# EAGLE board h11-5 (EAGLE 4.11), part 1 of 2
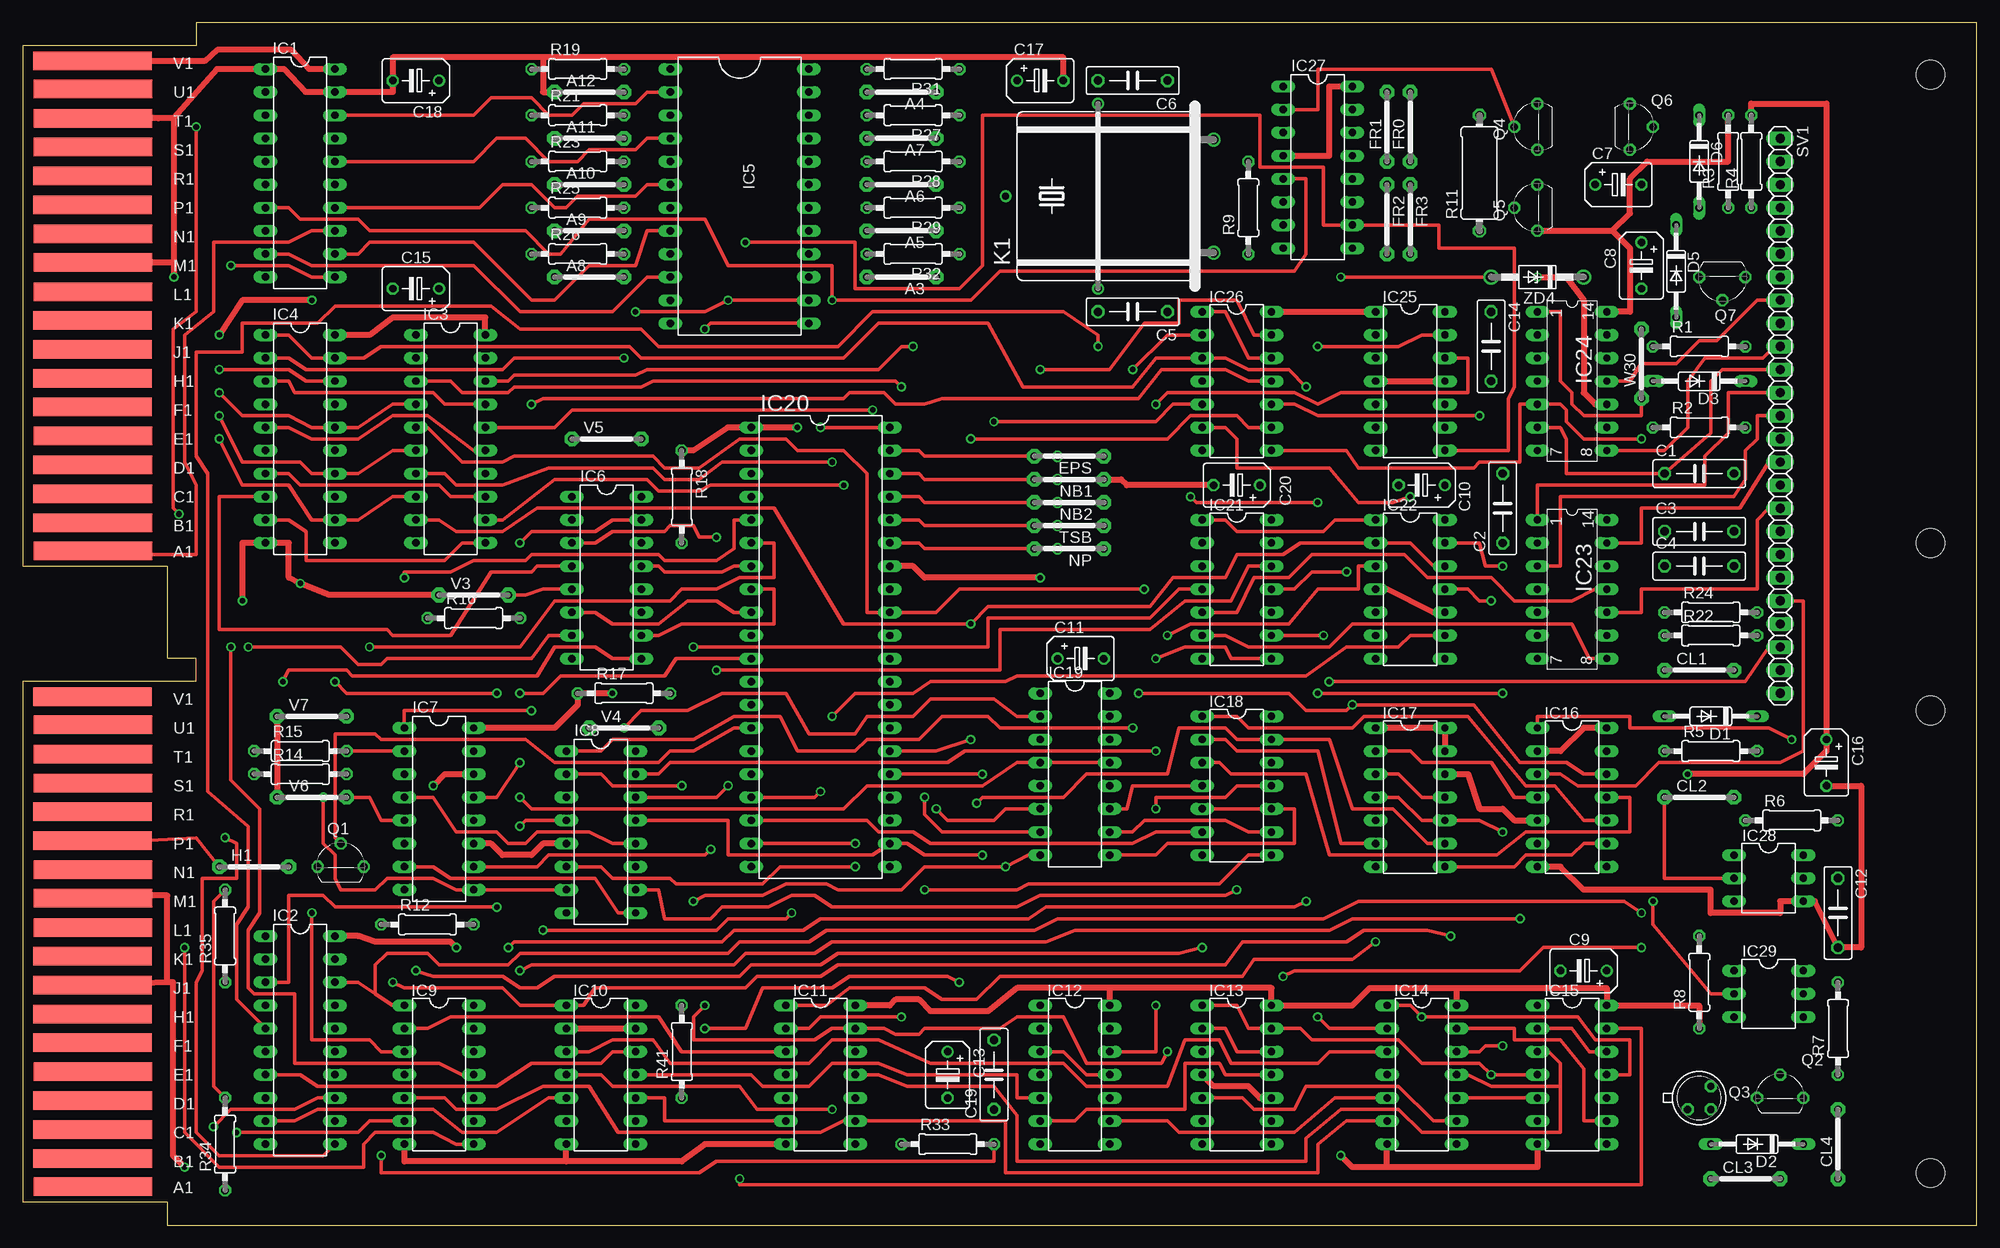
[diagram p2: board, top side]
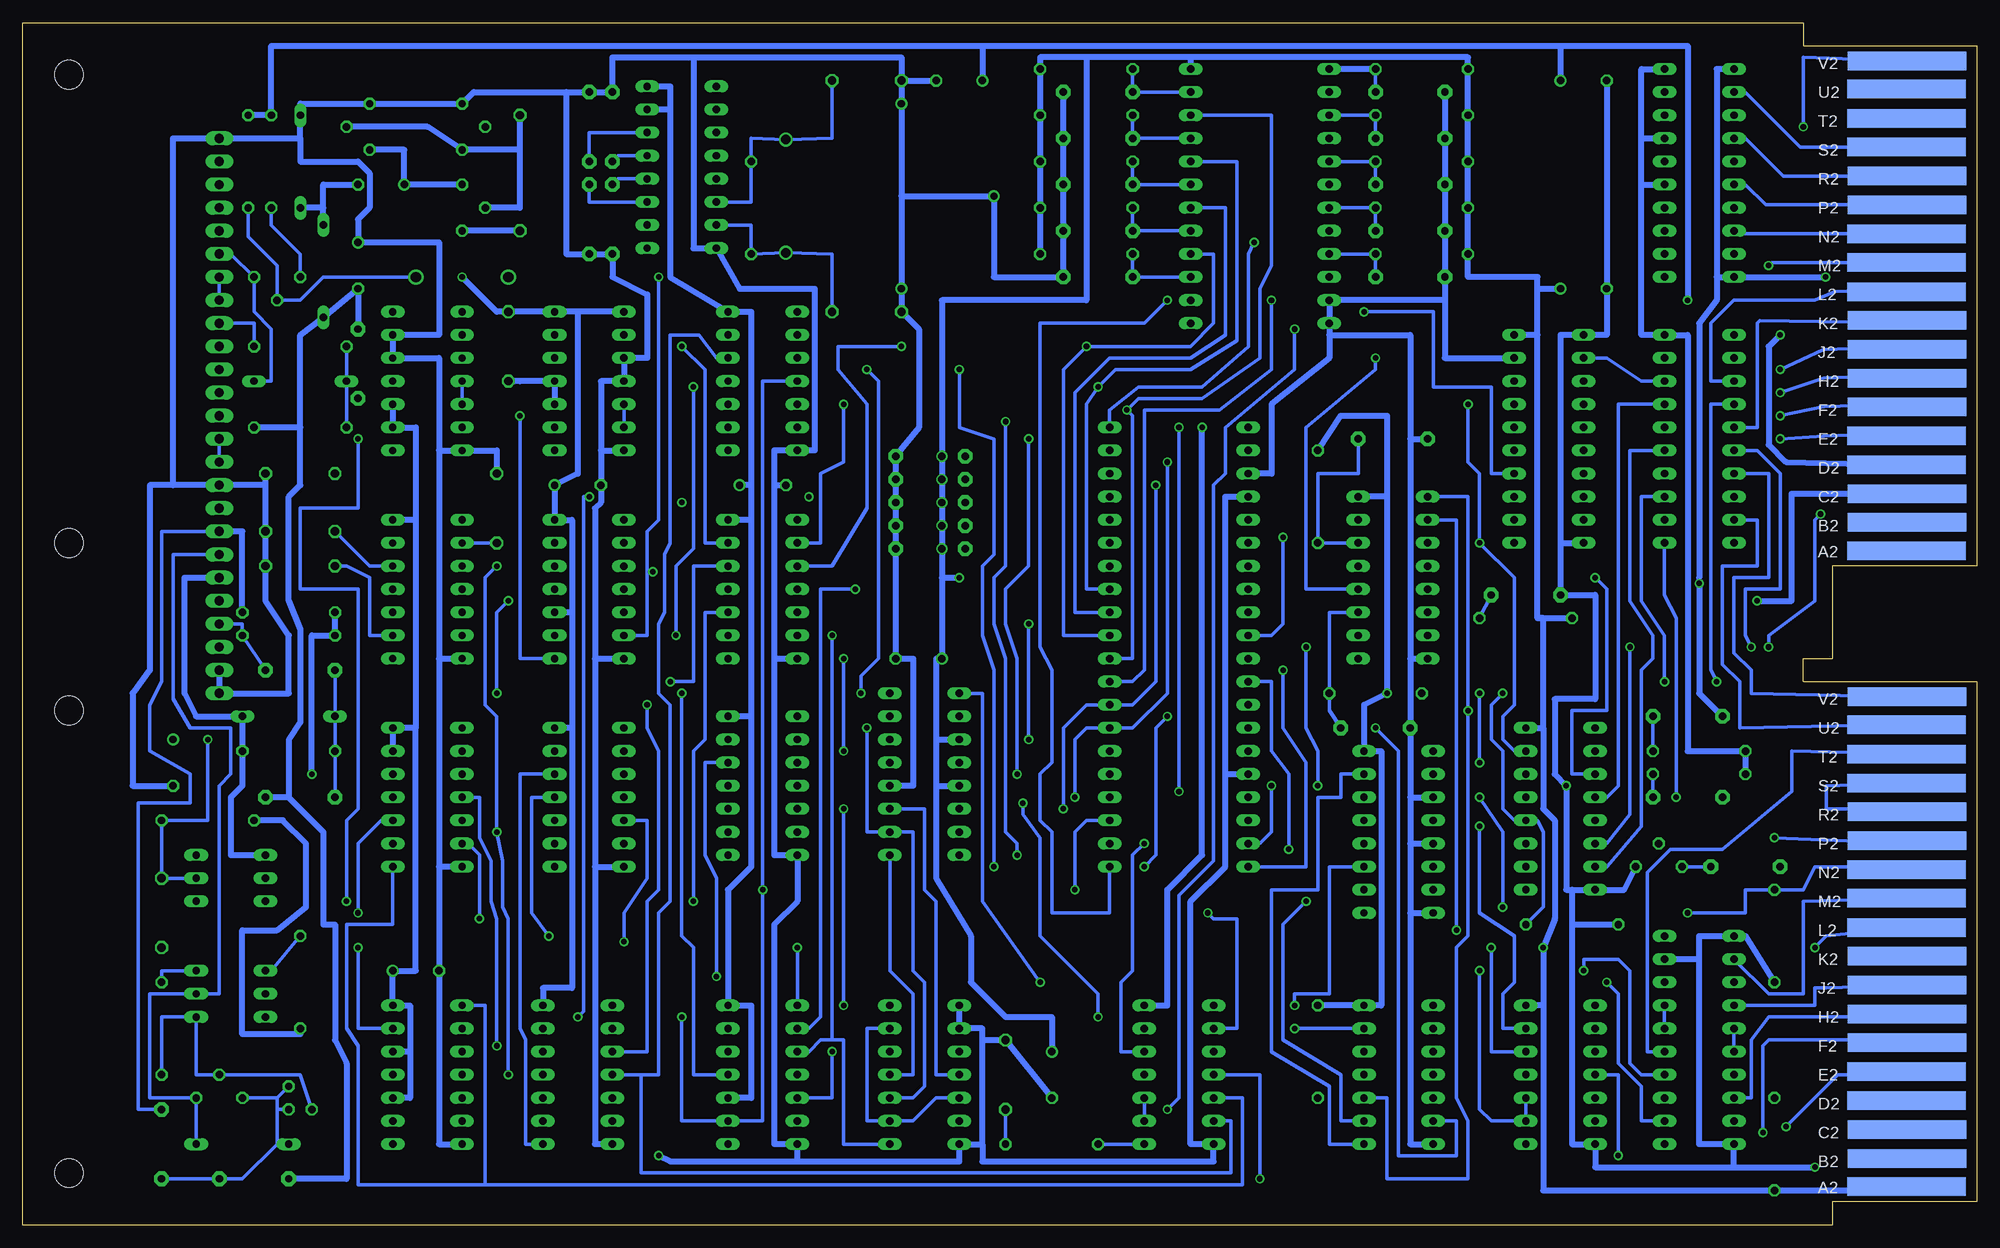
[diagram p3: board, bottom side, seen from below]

Size 214.63 x 132.08 mm. Coordinates in mm from the lower left corner, seen from the top.
Copper layers (1*16): Top 0.035mm / dielectric 1.5mm / Bottom 0.035mm
Design rules "15mils": minimum track width 15mil, minimum drill 24mil, track to track 15mil, track to pad 10mil, pad to pad 10mil, via to via 10mil, smd to smd 10mil, copper to edge 25mil, drill to drill 10mil, minimum pad ring 10mil, minimum via ring 8mil, stop-mask expansion 0mil, vias tented up to drill 0mil, thermal gap 10mil
Net classes: 1 Supply: width 0.635 mm

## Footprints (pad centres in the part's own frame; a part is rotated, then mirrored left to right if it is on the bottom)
07 = drill 0.813 pad 1.6 octagon: 1 -3.81,0; 2 3.81,0
C075-032X103 = drill 0.914 octagon: 1 -3.81,0; 2 3.81,0
B45181B = drill 0.813 round: + -2.54,0 | drill 0.813 octagon: - 2.54,0
DO35-10 = drill 0.813 long: A 5.08,0; C -5.08,0
DOUBLE-LONG = hole 3.175: 209.55,56.515; 209.55,5.715; 209.55,74.93; 209.55,126.365
EDGE-CON4 = smd 13.017 x 2.032: AA1 7.709,4.207; AB1 7.684,7.312; AC1 7.684,10.474; AD1 7.684,13.665; AE1 7.693,16.84; AF1 7.668,20.041; AH1 7.668,23.19; AJ1 7.668,26.34; AK1 7.668,29.515; AL1 7.693,32.69; AM1 7.693,35.89; AN1 7.693,39.04; AP1 7.668,42.24; AR1 7.668,45.39; AS1 7.693,48.565; AT1 7.693,51.74; AU1 7.693,54.94; AV1 7.668,58.026; BA1 7.709,74.057; BB1 7.684,77.162; BC1 7.684,80.324; BD1 7.684,83.515; BE1 7.693,86.69; BF1 7.668,89.891; BH1 7.668,93.04; BJ1 7.668,96.19; BK1 7.668,99.365; BL1 7.693,102.54; BM1 7.693,105.74; BN1 7.693,108.89; BP1 7.668,112.09; BR1 7.668,115.24; BS1 7.693,118.415; BT1 7.693,121.59; BU1 7.693,124.79; BV1 7.668,127.876 | smd 13.017 x 2.032 bottom: AA2 7.69,4.207; AB2 7.668,7.328; AC2 7.668,10.49; AD2 7.693,13.665; AE2 7.693,16.84; AF2 7.642,20.041; AH2 7.642,23.19; AJ2 7.668,26.34; AK2 7.668,29.515; AL2 7.693,32.69; AM2 7.693,35.89; AN2 7.693,39.04; AP2 7.668,42.24; AR2 7.668,45.39; AS2 7.693,48.565; AT2 7.693,51.74; AU2 7.693,54.966; AV2 7.668,58.026; BA2 7.69,74.057; BB2 7.668,77.178; BC2 7.668,80.34; BD2 7.693,83.515; BE2 7.693,86.69; BF2 7.642,89.891; BH2 7.642,93.04; BJ2 7.668,96.19; BK2 7.668,99.365; BL2 7.693,102.54; BM2 7.693,105.74; BN2 7.693,108.89; BP2 7.668,112.09; BR2 7.668,115.24; BS2 7.693,118.415; BT2 7.693,121.59; BU2 7.693,124.816; BV2 7.668,127.876
DIL20 = drill 0.813 long: 1 -11.43,-3.81; 2 -8.89,-3.81; 3 -6.35,-3.81; 4 -3.81,-3.81; 5 -1.27,-3.81; 6 1.27,-3.81; 7 3.81,-3.81; 8 6.35,-3.81; 9 8.89,-3.81; 10 11.43,-3.81; 11 11.43,3.81; 12 8.89,3.81; 13 6.35,3.81; 14 3.81,3.81; 15 1.27,3.81; 16 -1.27,3.81; 17 -3.81,3.81; 18 -6.35,3.81; 19 -8.89,3.81; 20 -11.43,3.81
DIL24 = drill 0.813 long: 1 -12.7,-7.62; 2 -10.16,-7.62; 3 -7.62,-7.62; 4 -5.08,-7.62; 5 -2.54,-7.62; 6 0,-7.62; 7 2.54,-7.62; 8 5.08,-7.62; 9 7.62,-7.62; 10 10.16,-7.62; 11 12.7,-7.62; 12 15.24,-7.62; 13 15.24,7.62; 14 12.7,7.62; 15 10.16,7.62; 16 7.62,7.62; 17 5.08,7.62; 18 2.54,7.62; 19 0,7.62; 20 -2.54,7.62; 21 -5.08,7.62; 22 -7.62,7.62; 23 -10.16,7.62; 24 -12.7,7.62
DIL16 = drill 0.813 long: 1 -8.89,-3.81; 2 -6.35,-3.81; 3 -3.81,-3.81; 4 -1.27,-3.81; 5 1.27,-3.81; 6 3.81,-3.81; 7 6.35,-3.81; 8 8.89,-3.81; 9 8.89,3.81; 10 6.35,3.81; 11 3.81,3.81; 12 1.27,3.81; 13 -1.27,3.81; 14 -3.81,3.81; 15 -6.35,3.81; 16 -8.89,3.81
DIL14 = drill 0.813 long: 1 -7.62,-3.81; 2 -5.08,-3.81; 3 -2.54,-3.81; 4 0,-3.81; 5 2.54,-3.81; 6 5.08,-3.81; 7 7.62,-3.81; 8 7.62,3.81; 9 5.08,3.81; 10 2.54,3.81; 11 0,3.81; 12 -2.54,3.81; 13 -5.08,3.81; 14 -7.62,3.81
DIL40 = drill 0.813 long: 1 -24.13,-7.62; 2 -21.59,-7.62; 3 -19.05,-7.62; 4 -16.51,-7.62; 5 -13.97,-7.62; 6 -11.43,-7.62; 7 -8.89,-7.62; 8 -6.35,-7.62; 9 -3.81,-7.62; 10 -1.27,-7.62; 11 1.27,-7.62; 12 3.81,-7.62; 13 6.35,-7.62; 14 8.89,-7.62; 15 11.43,-7.62; 16 13.97,-7.62; 17 16.51,-7.62; 18 19.05,-7.62; 19 21.59,-7.62; 20 24.13,-7.62; 21 24.13,7.62; 22 21.59,7.62; 23 19.05,7.62; 24 16.51,7.62; 25 13.97,7.62; 26 11.43,7.62; 27 8.89,7.62; 28 6.35,7.62; 29 3.81,7.62; 30 1.27,7.62; 31 -1.27,7.62; 32 -3.81,7.62; 33 -6.35,7.62; 34 -8.89,7.62; 35 -11.43,7.62; 36 -13.97,7.62; 37 -16.51,7.62; 38 -19.05,7.62; 39 -21.59,7.62; 40 -24.13,7.62
DIL14' = drill 0.8 long: 1 -7.62,-3.81; 2 -5.08,-3.81; 3 -2.54,-3.81; 4 0,-3.81; 5 2.54,-3.81; 6 5.08,-3.81; 7 7.62,-3.81; 8 7.62,3.81; 9 5.08,3.81; 10 2.54,3.81; 11 0,3.81; 12 -2.54,3.81; 13 -5.08,3.81; 14 -7.62,3.81
DIL06 = drill 0.813 long: 1 -2.54,-3.81; 2 0,-3.81; 3 2.54,-3.81; 4 2.54,3.81; 5 0,3.81; 6 -2.54,3.81
HC33U-H = drill 1.016 round: 1 -6.223,-5.08; 2 6.223,-5.08 | drill 0.813 round: M -10.16,7.62; M1 10.16,7.62
TO92L = drill 0.813 octagon: 1 2.54,0; 2 0,2.54; 3 -2.54,0
TO18E = drill 0.813 octagon: D 1.27,-1.27; G 1.27,1.27; S -1.27,-1.27
0207/10 = drill 0.813 octagon: 1 -5.08,0; 2 5.08,0
0411/12 = drill 0.914 octagon: 1 -6.35,0; 2 6.35,0
1X25 = drill 1.016 long: 1 -29.21,0; 2 -26.67,0; 3 -24.13,0; 4 -21.59,0; 5 -19.05,0; 6 -16.51,0; 7 -13.97,0; 8 -11.43,0; 9 -8.89,0; 10 -6.35,0; 11 -3.81,0; 12 -1.27,0; 13 1.27,0; 14 3.81,0; 15 6.35,0; 16 8.89,0; 17 11.43,0; 18 13.97,0; 19 16.51,0; 20 19.05,0; 21 21.59,0; 22 24.13,0; 23 26.67,0; 24 29.21,0; 25 31.75,0
DO41Z10 = drill 1.118 round: A 5.08,0; C -5.08,0

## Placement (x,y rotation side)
A3  J7MM  [07]  96.52,104.14 180 top
A4  J7MM  [07]  96.52,124.46 180 top
A5  J7MM  [07]  96.52,109.22 180 top
A6  J7MM  [07]  96.52,114.3 180 top
A7  J7MM  [07]  96.52,119.38 180 top
A8  J7MM  [07]  62.23,104.14 0 top
A9  J7MM  [07]  62.23,109.22 0 top
A10  J7MM  [07]  62.23,114.3 0 top
A11  J7MM  [07]  62.23,119.38 0 top
A12  J7MM  [07]  62.23,124.46 0 top
C1  [C075-032X103]  184.15,82.55 0 top
C2  [C075-032X103]  162.56,78.74 90 top
C3  [C075-032X103]  184.15,76.2 0 top
C4  [C075-032X103]  184.15,72.39 0 top
C5  [C075-032X103]  121.92,100.33 180 top
C6  [C075-032X103]  121.92,125.73 180 top
C7  [B45181B]  175.26,114.3 0 top
C8  [B45181B]  177.8,105.41 270 top
C9  [B45181B]  171.45,27.94 180 top
C10  [B45181B]  153.67,81.28 180 top
C11  [B45181B]  116.21,62.23 0 top
C12  [C075-032X103]  199.39,34.29 270 top
C13  [B45181B]  101.6,16.51 270 top
C14  [C075-032X103]  161.29,96.52 270 top
C15  [B45181B]  43.18,102.87 180 top
C16  [B45181B]  198.12,50.8 270 top
C17  [B45181B]  111.76,125.73 0 top
C18  [B45181B]  43.18,125.73 180 top
C19  [C075-032X103]  106.68,16.51 90 top
C20  [B45181B]  133.35,81.28 180 top
CL1  [07]  184.15,60.96 0 top
CL2  [07]  184.15,46.99 0 top
CL3  [07]  189.23,5.08 0 top
CL4  [07]  199.39,8.89 90 top
D1  1N4149  [DO35-10]  185.42,55.88 180 top
D2  1N4149  [DO35-10]  190.5,8.89 180 top
D3  1N4149  [DO35-10]  184.15,92.71 180 top
D5  1N4149  [DO35-10]  181.61,104.78 270 top
D6  1N4149  [DO35-10]  184.15,116.84 270 top
E$2  [DOUBLE-LONG]  0,0 0 top
EDGE$  [EDGE-CON4]  0,0 0 top
EPS  [07]  114.94,84.45 180 top
FR0  [07]  152.4,120.65 90 top
FR1  [07]  149.86,120.65 90 top
FR2  [07]  149.86,110.49 270 top
FR3  [07]  152.4,110.49 270 top
H1  J7MM  [07]  25.4,39.37 0 top
IC1  74LS240N  [DIL20]  30.48,115.57 270 top
IC2  74LS240N  [DIL20]  30.48,20.32 270 top
IC3  74LS240N  [DIL20]  46.99,86.36 270 top
IC4  74S240N  [DIL20]  30.48,86.36 270 top
IC5  8130  [DIL24]  78.74,114.3 270 top
IC6  74LS157N  [DIL16]  64.14,71.12 270 top
IC7  74LS257N  [DIL16]  45.72,45.72 270 top
IC8  74LS257N  [DIL16]  63.5,43.18 270 top
IC9  7438N  [DIL14]  45.72,16.51 270 top
IC10  74LS00N  [DIL14]  63.5,16.51 270 top
IC11  74LS08N  [DIL14]  87.63,16.51 270 top
IC12  74LS27N  [DIL14]  115.57,16.51 270 top
IC13  74LS74N  [DIL14]  133.35,16.51 270 top
IC14  74LS10N  [DIL14]  153.67,16.51 270 top
IC15  74LS74N  [DIL14]  170.18,16.51 270 top
IC16  74LS00N  [DIL14]  170.18,46.99 270 top
IC17  74LS74N  [DIL14]  152.4,46.99 270 top
IC18  74LS10N  [DIL14]  133.35,48.26 270 top
IC19  74LS75N  [DIL16]  115.57,49.53 270 top
IC20  6402  [DIL40]  87.63,63.5 270 top
IC21  74LS02N  [DIL14]  133.35,69.85 270 top
IC22  74LS74N  [DIL14]  152.4,69.85 270 top
IC23  1489N  [DIL14']  170.18,69.85 270 top
IC24  1488N  [DIL14']  170.18,92.71 270 top
IC25  74LS196  [DIL14]  152.4,92.71 270 top
IC26  74LS08N  [DIL14]  133.35,92.71 270 top
IC27  4702  [DIL16]  142.24,116.2 270 top
IC28  4N26  [DIL06]  191.77,38.1 270 top
IC29  4N26  [DIL06]  191.77,25.4 270 top
K1  2.4576Mhz  [HC33U-H]  125.73,113.03 90 top
NB1  [07]  114.94,81.92 180 top
NB2  [07]  114.94,79.38 180 top
NP  [07]  114.94,74.3 180 top
Q1  MPSA06  [TO92L]  34.93,39.37 0 top
Q2  MPSA55  [TO92L]  193.04,13.97 0 top
Q3  NCh, 30V, 1.5mA  [TO18E]  184.15,13.97 0 top
Q4  MPSA06  [TO92L]  166.37,120.65 90 top
Q5  MPSA06  [TO92L]  166.37,111.76 90 top
Q6  MPSA55  [TO92L]  176.53,120.65 270 top
Q7  MPSA55  [TO92L]  186.69,104.14 180 top
R1  [0207/10]  184.15,96.52 0 top
R2  [0207/10]  184.15,87.63 0 top
R3  [0207/10]  187.33,116.84 90 top
R4  [0207/10]  189.87,116.84 90 top
R5  [0207/10]  185.42,52.07 0 top
R6  [0207/10]  194.31,44.45 0 top
R7  [0207/10]  199.39,21.59 90 top
R8  [0207/10]  184.15,26.67 90 top
R9  [0207/10]  134.62,111.76 90 top
R11  [0411/12]  160.02,115.57 90 top
R12  [0207/10]  44.45,33.02 0 top
R14  [0207/10]  30.48,49.53 0 top
R15  [0207/10]  30.48,52.07 0 top
R16  [0207/10]  49.53,66.67 0 top
R17  [0207/10]  66.04,58.42 0 top
R18  [0207/10]  72.39,80.01 270 top
R19  [0207/10]  60.96,127 0 top
R21  [0207/10]  60.96,121.92 0 top
R22  [0207/10]  185.42,64.77 0 top
R23  [0207/10]  60.96,116.84 0 top
R24  [0207/10]  185.42,67.31 0 top
R25  [0207/10]  60.96,111.76 0 top
R26  [0207/10]  60.96,106.68 0 top
R27  [0207/10]  97.79,121.92 180 top
R28  [0207/10]  97.79,116.84 180 top
R29  [0207/10]  97.79,111.76 180 top
R31  [0207/10]  97.79,127 180 top
R32  [0207/10]  97.79,106.68 180 top
R33  [0207/10]  101.6,8.89 0 top
R34  [0207/10]  22.23,8.89 90 top
R35  [0207/10]  22.23,31.75 90 top
R41  [0207/10]  72.39,19.05 90 top
SV1  [1X25]  193.04,90.17 270 top
TSB  [07]  114.94,76.83 180 top
V3  [07]  49.53,69.22 0 top
V4  [07]  66.04,54.61 0 top
V5  [07]  64.14,86.36 0 top
V6  [07]  31.75,46.99 0 top
V7  [07]  31.75,55.88 0 top
W30  [07]  177.8,94.61 90 top
ZD4  1N4738A  [DO41Z10]  166.37,104.14 180 top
